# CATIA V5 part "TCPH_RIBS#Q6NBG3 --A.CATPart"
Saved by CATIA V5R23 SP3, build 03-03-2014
Part number: TCPH_RIBS#Q6NBFJ
Revision: --A
Nomenclature: _
Description: TCPH_RIBS
Property "AT": "PD"
Property "REP": "CM"
Property "External Part ID": "_"
Property "Description Modification": "CIMAFModel"
Property "PREF": "Y"
Property "LONG": "_"
Property "PBS 1": "24"
Property "PBS 2": "CR"
Property "PBS 3": "LC"
Property "DEPT": "_"
Property "DIVN": "_"
Property "GROUP": "_"
Property "UNIT": "_"
Property "PARTY": "_"
Property "RO": "---"
Property "RE": "SEKACHI"
Property "PRO": "---"
Property "Change Type": "Major"
Property "Maturity Level": "CD"
Property "Export Number": "_"
Property "Description Documents": "_"
Property "BOM": "_"
Property "ID": "Q6NBFJ"
Property "User In Enovia": "VAUQUEJ"
Property "Object Type": "_"
Property "CADENAS_ID": "_"
Property "Life Cycle Status": "Approved"
Bounding box of the stored display mesh (mm): x 13520 to 14219.978, y -1450 to 1450, z -6973 to -2778
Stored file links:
  C:\Users\pandeym\Desktop\__TCPH\TCPH_RIBS#Q6NBG3 --A.CATPart
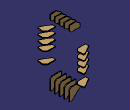
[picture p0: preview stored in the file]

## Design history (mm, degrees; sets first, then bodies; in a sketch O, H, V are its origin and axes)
Set1
  DatumSurface1 "SURFACE_IN"
Set2
  Sketch1 "TCPH_INNER_VERTICAL_RIB", origin (0, 0, 0), H (-1, 0, 0), V (0, 0, 1), geometry linked from another document
  Sketch2 "TCPH_INNER_HORIZONTAL_RIB", origin (0, 0, -4393), H (1, 0, 0), V (0, 1, 0), geometry linked from another document
Body1 (main body)
  Pad1: profile Sketch1, direction (0, 1, 0), length 25, mirrored extent
  RectPattern1: of the body so far, direction 1 instances 5, spacing 300, along edge [face of Pad1 | face of Pad1], Nu 3
  Pad2: profile Sketch2, direction (0, 0, 1), length 70, opposite side length -20
  RectPattern2: of Pad2, direction 1 instances 6, spacing 360, along edge [face of RectPattern1 | face of RectPattern1], Nu 2
  Split1: SplitPlane DatumSurface1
